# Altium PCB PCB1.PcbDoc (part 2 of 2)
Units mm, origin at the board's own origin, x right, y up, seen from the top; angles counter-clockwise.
Board outline 140.21 x 210.44 mm, 4 copper layers (Top Layer, Layer 1, Layer 2, Bottom Layer), stack 0.603 mm thick; 99 components, 45 nets, 371 pads, 603 vias.
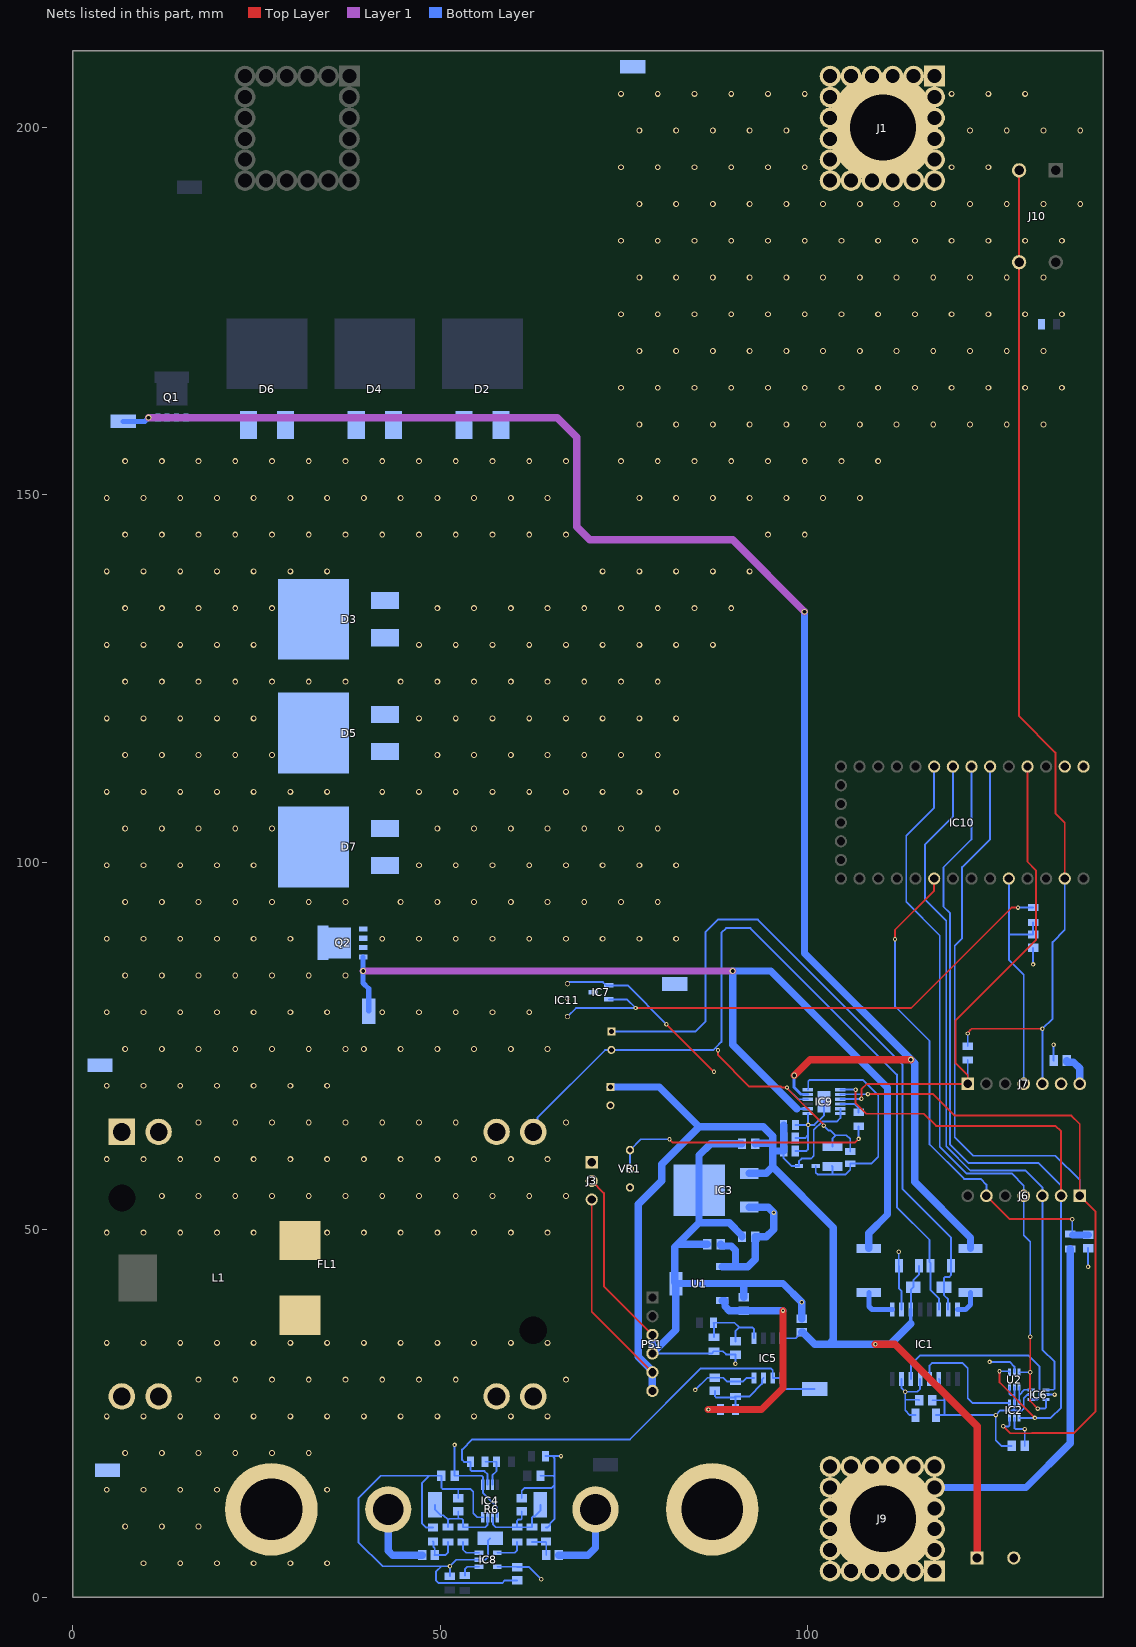
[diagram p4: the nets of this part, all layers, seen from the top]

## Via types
v1: diameter 0.8/0.8/0.8/0.8 (per signal layer), hole 0.5, Top Layer to Bottom Layer, 546 vias
v2: diameter 0.6, hole 0.3, Top Layer to Bottom Layer, 50 vias
v3: diameter 5, hole 5, Top Layer to Bottom Layer, 4 vias
v4: diameter 15, hole 9, Top Layer to Bottom Layer, 3 vias

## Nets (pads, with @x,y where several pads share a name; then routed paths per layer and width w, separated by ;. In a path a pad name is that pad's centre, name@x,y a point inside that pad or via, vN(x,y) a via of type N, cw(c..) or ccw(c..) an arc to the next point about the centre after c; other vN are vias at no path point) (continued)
ENABLE_PWM_HIN: IC2.3 IC9.2 IC10.28 J6.1 | length 164.4
  Top Layer w0.254: v2(108.204,68.453) 117.094,68.453 120.015,65.532 135.89,65.532 137.033,64.389 J6.1@137.033,54.61 139.192,52.451 139.192,25.273 136.271,22.352 130.556,22.352 130.51,22.306 127.554,22.306 v2(126.619,23.241)
  Bottom Layer w0.254: IC9.2@104.447,68.412 104.467,68.432 108.183,68.432 v2(108.204,68.453) ; IC10.28@124.841,113.03 124.841,103.169 121.031,99.359 121.031,89.662 120.015,88.646 120.015,62.611 122.555,60.071 133.731,60.071 137.033,56.769 J6.1@137.033,54.61 ; v2(126.619,23.241) 127.344,23.241 127.493,23.39 IC2.3@127.493,24.4
ENABLE_PWM_LIN: IC6.1 IC10.26 J6.3 | length 99.2
  Bottom Layer w0.254: IC10.26@119.761,113.03 119.761,106.208 115.933,102.38 115.951,102.362 115.951,94.996 118.872,92.075 118.872,61.341 122.165,58.048 129.658,58.048 131.953,55.753 131.953,33.655 133.604,32.004 133.604,28.358 133.455,28.209 IC6.1@132.445,28.209
FAULT_DRIVER: IC9.3 IC10.30 J7.1 R22.2 | length 71.1
  Top Layer w0.254: v2(107.315,67.818) 107.315,69.088 108.077,69.85 J7.1@121.793,69.85 121.793,70.993 120.142,72.644 120.142,78.486 131.064,89.408 131.064,98.933 129.921,100.076 IC10.30@129.921,113.03
  Bottom Layer w0.254: IC9.3@104.447,67.762 104.475,67.79 107.287,67.79 v2(107.315,67.818) ; J7.1@121.793,69.85 R22.2@121.793,73.091
GATE_Q1: IC9.11 Q1.4 R1.2 TP6.1 | length 229
  Top Layer w1: v1(98.171,70.993) 100.33,73.152 v1(114.046,73.152)
  Layer 1 w1: v1(10.287,160.528) 65.913,160.528 68.58,157.861 68.58,145.669 70.358,143.891 89.789,143.891 v1(99.568,134.112)
  Bottom Layer w0.254: Q1.4@11.536,160.528 Q1.4@11.557,160.549 ; IC9.11@100,68.435 IC9.11@100.023,68.412
  Bottom Layer w0.4: v1(98.171,70.993) 98.171,69.342 99.078,68.435 IC9.11@100,68.435
  Bottom Layer w0.7: TP6.1@6.858,160.02 9.779,160.02 v1(10.287,160.528) Q1.4@11.536,160.528
  Bottom Layer w1: v1(99.568,134.112) 99.568,87.63 114.554,72.644 114.554,56.515 122.174,48.895 R1.2@122.174,47.45
GATE_Q2: IC9.8 Q2.4 R2.2 TP12.1 | length 132.5
  Layer 1 w1: v1(39.497,85.217) v1(89.789,85.217)
  Bottom Layer w0.4: 98.511,66.462 IC9.8@100.023,66.462
  Bottom Layer w0.7: Q2.4@39.497,87.122 v1(39.497,85.217) 39.497,83.566 40.259,82.804 TP12.1@40.259,79.756
  Bottom Layer w1: 98.511,66.462 89.789,75.184 v1(89.789,85.217) 94.996,85.217 110.871,69.342 110.871,52.07 108.331,49.53 R2.2@108.331,47.45
GND: C1.2 C2.2 C3.2 C4.2 C5.2 C6.2 C7.2 C8.2 C9.2 C10.2 C11.2 C12.2 C13.2 C14.2 C15.2 C16.2 C17.2 C18.2 C21.2 C22.2 C25.2 C26.2 C27.2 D3.1 D3.3 D5.1 D5.3 D7.1 D7.3 IC1.2 IC1.13 IC1.15 IC2.2 IC3.2 IC4.4 IC5.4 IC6.2 IC7.3 IC8.2 IC9.7 IC9.13 IC10.32 IC11.2 J1.1 J1.2 J1.3 J1.4 J1.5 J1.6 J1.7 J1.8 J1.9 J1.10 J1.11 J1.12 J1.13 J1.14 J1.15 J1.16 J1.17 J1.18 J1.19 J1.20 J3.2 J7.6 J8.2 PS1.3 PS1.4 Q2.1 Q2.2 Q2.3 R5.2 R8.2 R10.2 R13.2 R14.2 R16.2 R20.2 TP2.1 TP8.1 TP11.1 U1.2 U1.4 U2.2 VR1.1 | length 267
  Top Layer w0.254: J3.2@70.612,56.642 72.263,54.991 72.263,42.291 PS1.3@78.867,35.687
  Bottom Layer w0.254: R20.2@49.022,9.459 48.072,9.459 47.498,10.033 47.498,15.494 48.514,16.51 ; R10.2@51.308,2.855 v2(51.308,4.191) ; C18.2@52.451,13.473 52.451,14.71 52.429,14.732 ; IC4.4@55.794,10.856 55.057,10.856 54.483,11.43 54.483,14.351 54.102,14.732 52.429,14.732 ; TP11.1@56.809,8.001 56.515,7.707 56.515,5.461 56.134,5.08 IC8.2@55.265,5.08 52.197,5.08 v2(51.308,4.191) ; C14.2@60.452,2.275 58.79,2.275 58.42,1.905 49.784,1.905 49.403,2.286 49.403,3.429 50.165,4.191 ; C15.2@61.087,13.473 61.087,14.478 61.468,14.859 65.151,14.859 65.532,15.24 ; C16.2@63.638,16.51 65.383,16.51 65.532,16.361 ; R13.2@64.323,19.177 65.278,19.177 ; R14.2@64.389,9.459 64.564,9.459 64.962,9.857 64.962,10.032 65.532,10.602 65.532,15.24 ; v2(66.425,19.181) 66.421,19.177 65.278,19.177 ; IC7.3@70.768,82.359 IC7.3@70.832,82.296 ; PS1.4@78.867,33.147 86.929,33.147 R8.2@87.249,33.467 88.453,33.467 88.9,33.02 90.159,33.02 C10.2@90.17,33.009 v2(90.17,31.75) ; v2(84.709,28.194) 86.371,29.856 C9.2@87.376,29.856 88.508,29.856 89.027,29.337 90.154,29.337 R5.2@90.17,29.321 91.17,29.321 91.649,29.8 IC5.4@92.71,29.8 ; C25.2@98.336,60.706 99.822,60.706 100.042,60.926 100.042,62.831 ; C27.2@98.336,62.484 99.695,62.484 100.042,62.831 ; C26.2@98.356,64.262 v2(100.076,64.262) ; IC9.7@100.023,65.812 100.023,64.315 v2(100.076,64.262) ; IC9.13@102.235,67.437 102.235,65.583 100.914,64.262 v2(100.076,64.262) ; v2(112.395,46.99) 112.395,45.102 C22.2@112.412,45.085 112.412,42.02 112.776,41.656 IC1.2@112.776,39.129 ; IC1.15@112.776,29.705 112.776,28.448 v2(113.284,27.94) ; C13.2@114.698,24.765 113.925,24.765 113.284,25.406 113.284,26.853 ; C5.2@115.178,26.797 115.122,26.853 113.284,26.853 ; IC1.13@115.316,29.705 115.316,28.321 114.935,27.94 v2(113.284,27.94) ; v2(124.76,32.004) 127.508,32.004 128.143,31.369 U2.2@128.143,30.591 ; IC2.2@128.143,24.4 128.143,23.009 128.292,22.86 v2(129.54,22.86) 129.54,20.585 C7.2@129.551,20.574 ; v2(130.683,86.106) C12.2@130.683,88.381 ; IC6.2@132.445,27.559 v2(133.604,27.559) ; C6.2@133.466,73.025 133.477,73.036 v2(133.477,75.184) ; v2(138.176,44.958) C11.2@138.176,47.487 ; 48.514,16.51 41.91,16.51 38.862,13.462 38.862,7.493 42.164,4.191 50.165,4.191 ; 48.514,16.51 C17.2@50.154,16.51 50.154,14.881 50.303,14.732 52.429,14.732 ; 50.165,4.191 v2(51.308,4.191) ; 65.278,19.177 65.532,18.923 65.532,16.361 ; 65.532,15.24 65.532,16.361 ; 100.042,62.831 100.042,64.228 v2(100.076,64.262) ; 113.284,26.853 v2(113.284,27.94)
  Bottom Layer w1: PS1.3@78.867,35.687 PS1.4@78.867,33.147 82.067,36.347 U1.4@82.067,42.672 ; C1.2@86.349,48.006 82.296,48.006 ; C3.2@91.062,49.022 91.062,49.172 89.307,50.927 85.217,50.927 ; C4.2@91.062,61.722 86.811,61.722 85.217,60.128 85.217,50.927 ; C2.2@91.313,40.778 91.313,42.672 ; C8.2@99.187,37.857 v2(99.187,40.132) 96.647,42.672 91.313,42.672 ; U1.4@82.067,42.672 81.915,42.824 81.915,47.625 82.296,48.006 ; U1.4@82.067,42.672 U1.2@88.367,42.672 91.313,42.672 ; 82.296,48.006 85.217,50.927
  other v1: 39.6,74.6 44.6,74.6 49.6,74.6 54.6,74.6 59.6,74.6 64.6,74.6 42.1,79.6 47.1,79.6 52.1,79.6 57.1,79.6 62.1,79.6 42.1,89.6 47.1,89.6 52.1,89.6 57.1,89.6 62.1,89.6 67.1,89.6 72.1,89.6 77.1,89.6 82.1,89.6 44.6,94.6 49.6,94.6 54.6,94.6 59.6,94.6 64.6,94.6 69.6,94.6 74.6,94.6 79.6,94.6 47.1,99.6 52.1,99.6 57.1,99.6 62.1,99.6 67.1,99.6 72.1,99.6 77.1,99.6 82.1,99.6 49.6,104.6 54.6,104.6 59.6,104.6 64.6,104.6 69.6,104.6 74.6,104.6 79.6,104.6 42.1,109.6 47.1,109.6 52.1,109.6 57.1,109.6 62.1,109.6 67.1,109.6 72.1,109.6 77.1,109.6 82.1,109.6 49.6,114.6 54.6,114.6 59.6,114.6 64.6,114.6 69.6,114.6 74.6,114.6 79.6,114.6 47.1,119.6 52.1,119.6 57.1,119.6 62.1,119.6 67.1,119.6 72.1,119.6 77.1,119.6 82.1,119.6 44.6,124.6 49.6,124.6 54.6,124.6 59.6,124.6 64.6,124.6 69.6,124.6 74.6,124.6 79.6,124.6 47.1,129.6 52.1,129.6 57.1,129.6 62.1,129.6 67.1,129.6 72.1,129.6 77.1,129.6 82.1,129.6 87.1,129.6 49.6,134.6 54.6,134.6 59.6,134.6 64.6,134.6 69.6,134.6 74.6,134.6 79.6,134.6 84.6,134.6 89.6,134.6 72.1,139.6 77.1,139.6 82.1,139.6 87.1,139.6 92.1,139.6 94.6,144.6 99.6,144.6 77.1,149.6 82.1,149.6 87.1,149.6 92.1,149.6 97.1,149.6 102.1,149.6 107.1,149.6 74.6,154.6 79.6,154.6 84.6,154.6 89.6,154.6 94.6,154.6 99.6,154.6 104.6,154.6 109.6,154.6 77.1,159.6 82.1,159.6 87.1,159.6 92.1,159.6 97.1,159.6 102.1,159.6 107.1,159.6 112.1,159.6 117.1,159.6 122.1,159.6 127.1,159.6 132.1,159.6 74.6,164.6 79.6,164.6 84.6,164.6 89.6,164.6 94.6,164.6 99.6,164.6 104.6,164.6 109.6,164.6 114.6,164.6 119.6,164.6 124.6,164.6 129.6,164.6 134.6,164.6 77.1,169.6 82.1,169.6 87.1,169.6 92.1,169.6 97.1,169.6 102.1,169.6 107.1,169.6 112.1,169.6 117.1,169.6 122.1,169.6 127.1,169.6 132.1,169.6 74.6,174.6 79.6,174.6 84.6,174.6 89.6,174.6 94.6,174.6 99.6,174.6 104.6,174.6 109.6,174.6 114.6,174.6 119.6,174.6 124.6,174.6 129.6,174.6 134.6,174.6 77.1,179.6 82.1,179.6 87.1,179.6 92.1,179.6 97.1,179.6 102.1,179.6 107.1,179.6 112.1,179.6 117.1,179.6 122.1,179.6 127.1,179.6 132.1,179.6 74.6,184.6 79.6,184.6 84.6,184.6 89.6,184.6 94.6,184.6 99.6,184.6 104.6,184.6 109.6,184.6 114.6,184.6 119.6,184.6 124.6,184.6 129.6,184.6 134.6,184.6 77.1,189.6 82.1,189.6 87.1,189.6 92.1,189.6 97.1,189.6 102.1,189.6 107.1,189.6 112.1,189.6 117.1,189.6 122.1,189.6 127.1,189.6 132.1,189.6 137.1,189.6 74.6,194.6 79.6,194.6 84.6,194.6 89.6,194.6 94.6,194.6 99.6,194.6 119.6,194.6 124.6,194.6 77.1,199.6 82.1,199.6 87.1,199.6 92.1,199.6 97.1,199.6 122.1,199.6 127.1,199.6 132.1,199.6 137.1,199.6 74.6,204.6 79.6,204.6 84.6,204.6 89.6,204.6 94.6,204.6 99.6,204.6 119.6,204.6 124.6,204.6 129.6,204.6
  other v4: 110.236,200.025
IN+AD8237: C15.1 IC4.2 R12.2 R21.2 TP9.1 | length 12.7
  Bottom Layer w0.254: IC4.2@57.094,10.856 57.192,10.758 57.192,9.864 57.547,9.509 R21.2@60.452,9.509 ; C15.1@61.087,11.673 61.087,10.69 60.938,10.541 60.601,10.541 60.452,10.392 R21.2@60.452,9.509 ; TP9.1@63.627,12.573 63.627,11.773 62.829,10.975 62.633,10.975 62.484,10.826 R12.2@62.484,9.509 R21.2@60.452,9.509
IN-AD8237: C18.1 IC4.3 R11.2 R19.2 TP10.1 | length 12.8
  Bottom Layer w0.254: TP10.1@49.276,12.573 49.276,11.938 50.074,11.14 50.433,11.14 51.054,10.519 ; R19.2@51.054,9.509 51.054,10.519 ; C18.1@52.451,11.673 52.451,10.817 52.6,10.668 ; IC4.3@56.444,10.856 56.444,9.835 56.118,9.509 R11.2@53.086,9.509 53.086,10.519 52.937,10.668 52.6,10.668 ; 51.054,10.519 51.203,10.668 52.6,10.668
NetC9_1: C9.1 IC5.3 R4.2 R5.1 | length 10.6
  Bottom Layer w0.254: C9.1@87.376,28.056 87.376,27.327 87.525,27.178 90.027,27.178 R5.1@90.17,27.321 ; R4.2@90.154,25.527 90.17,25.543 R5.1@90.17,27.321 ; IC5.3@93.98,29.8 93.782,29.602 93.782,29.012 92.091,27.321 R5.1@90.17,27.321
NetC10_1: C10.1 IC5.5 R7.2 R8.1 | length 11.2
  Bottom Layer w0.254: R8.1@87.249,35.367 87.249,37.272 R7.2@87.183,37.338 90.043,37.338 90.678,36.703 ; C10.1@90.17,34.809 90.17,36.195 90.678,36.703 ; IC5.5@92.71,35.224 92.71,36.449 92.456,36.703 90.678,36.703
NetC19_1: C19.1 C20.1 D1.1 IC1.7 | length 98.3
  Bottom Layer w0.254: C19.1@73.279,76.962 84.709,76.962 86.106,78.359 86.106,90.551 87.757,92.202 93.218,92.202 112.903,72.517 112.903,55.565 119.49,48.978 C20.1@119.49,45.085 119.49,43.798 119.253,43.561 118.708,43.561 118.559,43.412 D1.1@118.559,42.164 118.559,41.08 119.126,40.513 IC1.7@119.126,39.129
NetC23_2: C23.2 C24.2 D8.1 IC9.12 | length 32.2
  Bottom Layer w0.254: IC9.12@100.023,69.062 100.076,69.115 100.076,70.209 100.225,70.358 107.569,70.358 109.601,68.326 109.601,59.944 108.654,58.997 C24.2@105.791,58.997 105.791,58.166 105.156,57.531 103.527,57.531 ; D8.1@101.099,58.674 101.099,57.778 101.346,57.531 103.527,57.531 ; C23.2@103.298,58.674 C23.2@103.378,58.594 103.378,57.68 103.527,57.531
NetFB1_2: FB1.2 R12.1 R14.1 | length 3.7
  Bottom Layer w0.254: R12.1@62.484,7.509 64.339,7.509 64.428,7.42 FB1.2@64.428,5.715
NetFB2_2: FB2.2 R19.1 R20.1 | length 5.3
  Bottom Layer w0.254: R20.1@49.022,7.559 49.1,7.481 49.1,6.802 49.254,6.648 49.254,5.732 FB2.2@49.237,5.715 50.673,5.715 51.054,6.096 R19.1@51.054,7.509
NetFL1_A2: FL1.A2 FL1.A4 FL1.B2 FL1.B4 L1.1 R6.MH1 TP7.1
  other v1: 9.6,4.6 14.6,4.6 19.6,4.6 24.6,4.6 29.6,4.6 34.6,4.6 7.1,9.6 12.1,9.6 17.1,9.6 4.6,14.6 9.6,14.6 14.6,14.6 19.6,14.6 34.6,14.6 7.1,19.6 12.1,19.6 17.1,19.6 22.1,19.6 27.1,19.6 32.1,19.6 4.6,24.6 9.6,24.6 14.6,24.6 19.6,24.6 24.6,24.6 29.6,24.6 34.6,24.6 39.6,24.6 44.6,24.6 49.6,24.6 54.6,24.6 59.6,24.6 64.6,24.6 17.1,29.6 22.1,29.6 27.1,29.6 32.1,29.6 37.1,29.6 42.1,29.6 47.1,29.6 52.1,29.6 67.1,29.6 4.6,34.6 9.6,34.6 14.6,34.6 19.6,34.6 24.6,34.6 29.6,34.6 34.6,34.6 39.6,34.6 44.6,34.6 49.6,34.6 54.6,34.6 59.6,34.6 64.6,34.6
NetIC1_1: IC1.1 R2.1 | length 5.3
  Bottom Layer w0.7: R2.1@108.331,41.45 108.331,39.539 108.741,39.129 IC1.1@111.506,39.129
NetIC1_8: IC1.8 R1.1 | length 3.7
  Bottom Layer w0.7: IC1.8@120.396,39.129 121.504,39.129 122.174,39.799 R1.1@122.174,41.45
NetIC1_12: IC1.12 IC2.4 | length 17.5
  Bottom Layer w0.254: IC1.12@116.586,29.705 116.586,31.496 116.967,31.877 121.031,31.877 121.793,31.115 121.793,27.051 122.444,26.4 IC2.4@127.493,26.4
NetIC1_14: IC1.14 IC6.4 | length 26
  Bottom Layer w0.254: IC1.14@114.046,29.705 114.046,31.623 115.316,32.893 130.048,32.893 131.572,31.369 131.572,27.178 131.303,26.909 IC6.4@130.445,26.909
NetIC2_6: IC2.6 IC6.6 U2.4 | length 4.1
  Bottom Layer w0.254: IC2.6@128.793,26.4 128.793,27.495 ; U2.4@128.793,28.591 128.793,27.495 ; IC6.6@130.445,28.209 129.507,28.209 128.793,27.495
NetIC4_7: IC4.7 R15.2 R18.1 | length 4.9
  Bottom Layer w0.254: R15.2@56.118,18.415 R18.1@57.674,18.415 57.674,17.161 57.094,16.581 IC4.7@57.094,15.306
NetIC7_2: IC7.2 IC11.1 R17.1 | length 73.7
  Top Layer w0.254: v2(76.581,80.175) 114.084,80.175 127.746,93.837 v2(128.635,93.837)
  Bottom Layer w0.254: IC11.1@67.31,79 68.485,80.175 v2(76.581,80.175) 75.41,81.346 IC7.2@72.932,81.346 ; v2(128.635,93.837) R17.1@130.683,93.837
NetIC8_1: IC8.1 R9.1 | length 3
  Bottom Layer w0.254: R9.1@53.34,2.905 53.34,3.81 53.66,4.13 IC8.1@55.265,4.13
NetIC8_3: IC8.3 R11.1 | length 3.4
  Bottom Layer w0.254: R11.1@53.086,7.509 53.086,6.477 53.533,6.03 IC8.3@55.265,6.03
NetIC8_4: IC8.4 R21.1 | length 4
  Bottom Layer w0.254: IC8.4@57.765,6.03 60.132,6.03 60.452,6.35 R21.1@60.452,7.509
NetIC9_4: IC9.4 R23.1 | length 3.3
  Bottom Layer w0.254: IC9.4@104.447,67.112 106.333,67.112 106.934,66.511 R23.1@106.934,65.974
NetR23_2: R23.2 VR1.2 VR1.3 | length 36.4
  Top Layer w0.254: v2(81.199,62.311) 81.661,61.849 106.426,61.849 v2(106.934,62.357)
  Bottom Layer w0.254: VR1.2@75.819,58.293 VR1.3@75.819,60.833 77.297,62.311 v2(81.199,62.311) ; v2(106.934,62.357) R23.2@106.934,64.074
PWM_MC_SIGNAL_HIN: IC2.1 IC9.1 IC10.27 J6.2 U2.1 | length 159.4
  Top Layer w0.254: v2(106.527,69.062) 106.527,67.209 107.95,65.786 115.824,65.786 117.475,64.135 133.731,64.135 134.493,63.373 J6.2@134.493,54.61 ; v2(126.111,30.734) 126.111,29.21 v2(130.937,24.384)
  Bottom Layer w0.254: IC9.1@104.447,69.062 v2(106.527,69.062) ; IC10.27@122.301,113.03 122.301,103.124 118.491,99.314 118.491,93.98 119.38,93.091 119.38,61.595 121.92,59.055 131.445,59.055 134.493,56.007 J6.2@134.493,54.61 134.493,25.781 133.096,24.384 v2(130.937,24.384) 128.809,24.384 IC2.1@128.793,24.4 ; v2(126.111,30.734) 127.42,30.734 127.493,30.661 U2.1@127.493,30.591
PWM_MC_SIGNAL_LIN: IC6.3 IC10.25 J6.4 U2.3 | length 103.7
  Top Layer w0.254: v2(130.302,35.433) 130.294,35.425 130.294,30.599 v2(130.286,30.591) 130.286,26.686 v2(131.318,25.654)
  Bottom Layer w0.254: IC10.25@117.221,113.03 117.221,107.442 113.411,103.632 113.411,94.615 117.983,90.043 117.983,61.301 121.617,57.667 127.753,57.667 129.413,56.007 J6.4@129.413,54.61 129.413,49.276 130.302,48.387 v2(130.302,35.433) ; U2.3@128.793,30.591 v2(130.286,30.591) ; v2(131.318,25.654) 132.24,25.654 132.445,25.859 IC6.3@132.445,26.909
R_SHUNT+: FB1.1 R6.2 | length 10.6
  Bottom Layer w1: FB1.1@66.128,5.715 70.104,5.715 71.12,6.731 R6.2@71.12,11.938
R_SHUNT-: FB2.1 R6.1 | length 10.5
  Bottom Layer w1: R6.1@42.92,11.938 42.92,6.301 43.506,5.715 FB2.1@47.537,5.715
REF_1.5V: IC4.6 IC5.1 IC5.2 R15.1 TP3.1 | length 62.7
  Bottom Layer w0.254: IC4.6@56.444,15.306 56.444,16.708 56.007,17.145 54.251,17.145 54.102,17.294 54.102,18.399 53.229,18.399 52.959,18.669 52.959,20.066 54.356,21.463 75.819,21.463 85.471,31.115 94.996,31.115 95.25,30.861 IC5.2@95.25,29.8 IC5.1@96.52,29.8 96.52,28.702 96.901,28.321 TP3.1@100.965,28.321
SUPERCAPACITOR_SENSE: C11.1 IC10.9 J6.6 R3.2 | length 69.1
  Top Layer w0.254: v2(111.887,89.535) 111.887,90.805 117.221,96.139 IC10.9@117.221,97.79 ; J6.6@124.333,54.61 127.508,51.435 v2(136.017,51.435)
  Bottom Layer w0.254: v2(111.887,89.535) 111.887,80.391 116.586,75.692 116.586,61.621 121.301,56.905 123.562,56.905 124.333,56.134 J6.6@124.333,54.61 ; v2(136.017,51.435) 136.017,49.333 R3.2@136.063,49.287
  Bottom Layer w1: R3.2@136.063,49.287 C11.1@138.176,49.287
SUPERCAPACITOR_V+: J9.1 J9.2 J9.3 J9.4 J9.5 J9.6 J9.7 J9.8 J9.9 J9.10 J9.11 J9.12 J9.13 J9.14 J9.15 J9.16 J9.17 J9.18 J9.19 J9.20 R3.1 R6.MH2 | length 47.4
  Bottom Layer w1: J9.5@117.263,14.916 129.724,14.916 135.763,20.955 R3.1@135.763,47.387
  other v4: 110.236,10.668
SW_NET: C19.2 C20.2 C23.1 C24.1 D2.1 D2.3 D3.2 D4.1 D4.3 D5.2 D6.1 D6.3 D7.2 FL1.A1 FL1.A3 FL1.B1 FL1.B3 IC1.6 IC9.10 L1.2 Q1.1 Q1.2 Q1.3 Q2.5 Q2.6 TP5.1 | length 144.1
  Top Layer w0.254: v2(87.795,74.422) 87.803,74.414 87.803,73.741 92.075,69.469 96.38,69.469 96.491,69.358 v2(97.188,69.358) ; v2@97.282,69.406 97.255,69.379 97.255,69.199 102.197,64.257 v2(102.197,64.165)
  Bottom Layer w0.254: FL1.B3@62.658,63.305 63.254,63.901 63.254,65.286 72.43,74.462 C19.2@73.279,74.462 73.299,74.442 87.102,74.442 87.122,74.422 87.458,74.758 ; v2(87.795,74.422) 87.458,74.758 ; v2(97.188,69.358) 97.188,69.265 98.691,67.762 IC9.10@100.023,67.762 ; v2(102.197,64.165) 102.88,63.482 103.142,63.482 103.759,62.865 ; C23.1@103.378,61.294 103.378,62.39 103.759,62.771 103.759,62.865 ; C24.1@105.791,60.637 105.791,62.357 105.283,62.865 103.759,62.865 ; IC1.6@117.856,39.129 117.856,40.64 116.73,41.766 116.73,45.46 116.586,45.604 116.586,48.641 112.141,53.086 112.141,71.12 92.202,91.059 88.9,91.059 88.265,90.424 88.265,75.565 87.458,74.758
  other v1: 4.6,49.6 9.6,49.6 14.6,49.6 19.6,49.6 24.6,49.6 34.6,49.6 39.6,49.6 44.6,49.6 49.6,49.6 54.6,49.6 59.6,49.6 64.6,49.6 12.1,54.6 17.1,54.6 22.1,54.6 27.1,54.6 32.1,54.6 37.1,54.6 42.1,54.6 47.1,54.6 52.1,54.6 57.1,54.6 62.1,54.6 67.1,54.6 4.6,59.6 9.6,59.6 14.6,59.6 19.6,59.6 24.6,59.6 29.6,59.6 34.6,59.6 39.6,59.6 44.6,59.6 49.6,59.6 54.6,59.6 59.6,59.6 64.6,59.6 17.1,64.6 22.1,64.6 27.1,64.6 32.1,64.6 37.1,64.6 42.1,64.6 47.1,64.6 52.1,64.6 67.1,64.6 4.6,69.6 9.6,69.6 14.6,69.6 19.6,69.6 24.6,69.6 29.6,69.6 34.6,69.6 7.1,74.6 12.1,74.6 17.1,74.6 22.1,74.6 27.1,74.6 32.1,74.6 37.1,74.6 4.6,79.6 9.6,79.6 14.6,79.6 19.6,79.6 24.6,79.6 29.6,79.6 34.6,79.6 7.1,84.6 12.1,84.6 17.1,84.6 22.1,84.6 27.1,84.6 32.1,84.6 37.1,84.6 4.6,89.6 9.6,89.6 14.6,89.6 19.6,89.6 24.6,89.6 29.6,89.6 7.1,94.6 12.1,94.6 17.1,94.6 22.1,94.6 27.1,94.6 32.1,94.6 37.1,94.6 4.6,99.6 9.6,99.6 14.6,99.6 19.6,99.6 24.6,99.6 7.1,104.6 12.1,104.6 17.1,104.6 22.1,104.6 27.1,104.6 4.6,109.6 9.6,109.6 14.6,109.6 19.6,109.6 24.6,109.6 29.6,109.6 34.6,109.6 7.1,114.6 12.1,114.6 17.1,114.6 22.1,114.6 27.1,114.6 4.6,119.6 9.6,119.6 14.6,119.6 19.6,119.6 24.6,119.6 7.1,124.6 12.1,124.6 17.1,124.6 22.1,124.6 27.1,124.6 32.1,124.6 37.1,124.6 4.6,129.6 9.6,129.6 14.6,129.6 19.6,129.6 24.6,129.6 7.1,134.6 12.1,134.6 17.1,134.6 22.1,134.6 27.1,134.6 4.6,139.6 9.6,139.6 14.6,139.6 19.6,139.6 24.6,139.6 29.6,139.6 34.6,139.6 7.1,144.6 12.1,144.6 17.1,144.6 22.1,144.6 27.1,144.6 32.1,144.6 37.1,144.6 42.1,144.6 47.1,144.6 52.1,144.6 57.1,144.6 62.1,144.6 67.1,144.6 4.6,149.6 9.6,149.6 14.6,149.6 19.6,149.6 24.6,149.6 29.6,149.6 34.6,149.6 39.6,149.6 44.6,149.6 49.6,149.6 54.6,149.6 59.6,149.6 64.6,149.6 7.1,154.6 12.1,154.6 17.1,154.6 22.1,154.6 27.1,154.6 32.1,154.6 37.1,154.6 42.1,154.6 47.1,154.6 52.1,154.6 57.1,154.6 62.1,154.6 67.1,154.6
TEMP_SENSOR: C12.1 IC10.5 J7.4 R17.2 | length 33.7
  Bottom Layer w0.254: IC10.5@127.381,97.79 127.381,90.181 ; J7.4@129.413,69.85 129.413,84.709 127.381,86.741 127.381,90.181 ; R17.2@130.683,91.837 C12.1@130.683,90.181 127.381,90.181
VCC_3V: C2.1 C5.1 C7.1 C13.1 IC1.11 IC2.5 IC6.5 R4.1 U1.3 U2.5 U2.6 | length 65.6
  Top Layer w1: v2(86.487,25.527) 93.726,25.527 96.647,28.448 v2(96.647,38.989)
  Bottom Layer w0.254: v2(86.487,25.527) R4.1@88.154,25.527 ; C2.1@91.302,38.989 C2.1@91.313,38.978 ; C5.1@116.978,26.797 118.618,26.797 ; C13.1@117.458,24.765 118.618,24.765 ; IC1.11@117.856,29.705 117.921,29.64 117.921,28.51 118.618,27.813 118.618,26.797 ; U2.6@127.493,28.591 127.493,27.644 127.642,27.495 128.143,27.495 ; C7.1@127.751,20.574 126.365,20.574 125.603,21.336 v2(125.603,24.765) ; U2.5@128.143,28.591 128.143,27.495 ; IC6.5@130.445,27.559 130.372,27.486 129.848,27.486 129.413,27.051 129.413,25.654 129.159,25.4 127.889,25.4 ; 118.618,24.765 118.618,26.797 ; 118.618,24.765 v2(125.603,24.765) ; v2(125.603,24.765) 126.238,25.4 127.889,25.4 ; 127.889,25.4 128.143,25.654 IC2.5@128.143,26.4 128.143,27.495
  Bottom Layer w1: U1.3@88.367,40.372 88.392,40.347 88.742,40.347 88.742,39.575 89.328,38.989 C2.1@91.302,38.989 ; C2.1@91.313,38.978 96.636,38.978 v2(96.647,38.989)
VCC_3V_MCU: IC10.2 J7.5 J10.3 J10.4 R22.1 | length 140.4
  Top Layer w0.254: v2(121.793,76.708) 121.793,76.802 122.121,77.13 122.121,77.163 122.301,77.343 v2(131.953,77.343) ; J10.3@128.778,194.183 J10.4@128.778,181.683 128.778,119.888 133.731,114.935 133.731,106.68 135.001,105.41 IC10.2@135.001,97.79
  Bottom Layer w0.254: R22.1@121.793,74.991 v2(121.793,76.708) ; J7.5@131.953,69.85 v2(131.953,77.343) 133.35,78.74 133.35,89.154 135.001,90.805 IC10.2@135.001,97.79
VCC_5V: C1.1 C3.1 C6.1 C14.1 C17.1 IC3.3 IC4.1 IC4.5 IC7.1 IC8.5 IC10.33 IC11.3 J3.1 J7.7 U1.1 | length 72.1
  Top Layer w0.254: v2(80.772,77.978) v2(87.249,71.501)
  Bottom Layer w0.254: v2(51.954,20.712) C17.1@51.954,16.51 55.626,16.51 55.794,16.342 IC4.5@55.794,15.306 55.794,14.183 57.744,12.233 IC4.1@57.744,10.856 ; IC8.5@57.765,4.13 60.397,4.13 C14.1@60.452,4.075 62.092,4.075 v2(63.754,2.413) ; IC11.3@67.31,83.48 67.523,83.693 72.135,83.693 72.582,83.246 IC7.1@72.932,83.246 75.504,83.246 v2(80.772,77.978)
  Bottom Layer w1: C1.1@88.149,48.006 88.149,47.856 88.224,47.781 89.584,47.781 90.17,47.195 90.17,45.041 90.101,44.972 ; U1.1@88.367,44.972 90.101,44.972 ; IC3.3@92.067,53.072 94.629,53.072 v2(95.377,52.324) 95.377,50.038 94.361,49.022 C3.1@92.862,49.022 92.862,45.999 91.835,44.972 90.101,44.972 ; C6.1@135.266,73.025 135.266,72.875 135.341,72.8 136.193,72.8 137.033,71.96 J7.7@137.033,69.85
VCC_12V: C4.1 C8.1 C21.1 C22.1 C25.1 C26.1 C27.1 D1.2 D8.2 IC1.3 IC3.1 IC5.8 IC9.5 IC9.6 J3.3 J8.1 PS1.5 PS1.6 | length 214.5
  Top Layer w0.254: J3.3@70.612,54.102 70.612,38.862 PS1.5@78.867,30.607
  Top Layer w1: v2(109.22,34.417) 111.887,34.417 123.063,23.241 J8.1@123.063,5.334
  Bottom Layer w0.254: IC5.8@96.52,35.224 98.354,35.224 C8.1@98.962,35.832 ; C26.1@96.716,64.262 C26.1@96.736,64.242 ; C25.1@96.736,60.931 C25.1@96.736,60.706 96.736,59.728 97.79,58.674 D8.2@98.799,58.674 98.799,59.302 99.187,59.69 100.457,59.69 100.838,60.071 100.838,63.589 101.968,64.719 103.96,64.719 104.447,65.206 IC9.6@104.447,65.812 IC9.5@104.447,66.462 ; IC1.3@114.046,39.129 114.046,41.851 D1.2@114.359,42.164 114.418,42.223 114.418,43.171 115.172,43.925 C22.1@115.172,45.085
  Bottom Layer w0.5: 114.046,37.211 IC1.3@114.046,39.129
  Bottom Layer w1: C21.1@73.152,69.429 79.796,69.429 85.217,64.008 85.232,64.008 ; PS1.6@78.867,28.067 PS1.5@78.867,30.607 78.867,30.787 76.962,32.692 76.962,53.467 80.137,56.642 80.137,58.913 85.232,64.008 ; IC3.1@92.067,57.672 94.375,57.672 95.25,58.547 ; C4.1@92.862,61.722 92.912,61.722 92.937,61.747 95.25,61.747 ; C25.1@96.736,60.706 95.25,60.706 ; C25.1@96.736,60.931 C27.1@96.736,62.484 C26.1@96.736,64.242 ; C8.1@99.187,36.057 99.337,36.057 100.977,34.417 102.919,34.417 ; 114.046,37.211 111.252,34.417 v2(109.22,34.417) 102.919,34.417 ; 85.232,64.008 93.98,64.008 95.25,62.738 95.25,61.747 ; 95.25,58.547 95.25,60.706 ; 95.25,58.547 103.505,50.292 103.505,35.003 102.919,34.417 ; 95.25,60.706 95.25,61.747
pads on no net: FL1.1 FL1.2 IC1.4 IC1.5 IC1.9 IC1.10 IC1.16 IC9.9 IC10.1 IC10.3 IC10.4 IC10.7 IC10.8 IC10.11 IC10.12 IC10.13 IC10.14 IC10.15 IC10.16 IC10.17 IC10.18 IC10.19 IC10.20 IC10.21 IC10.22 IC10.23 IC10.31 L1.3
copper on no net:
  other v3: 5,5 135,5 5,205 135,205

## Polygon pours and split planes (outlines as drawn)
GND on Top Layer "GND" (solid, pour order 36): 73.533,210.185 139.827,210.185 139.827,184 139.827,181.494 139.827,155.067 115.062,155.067 84.963,124.968 84.963,81.28 68.707,81.28 66.167,78.74 66.167,73.279 65.405,72.517 38.481,72.517 38.481,84.582 38.481,87.88 38.481,91.694 40.64,93.853 40.64,137.922 42.291,139.573 69.977,139.573 73.533,143.129
NetFL1_A2 on Top Layer "Top Layer-NetFL1_A2" (solid, pour order 6): 1,1 36.576,1 36.576,22 68,22 68,42 25,42 25,39 1,39
SW_NET on Top Layer "GND" (solid, pour order 44): 0,161.544 65.151,161.544 68.453,158.242 68.453,141.097 39.37,141.097 37.846,139.573 37.846,68.961 65.659,68.961 67.818,66.802 67.818,45.72 1.524,45.72 0,47.244
BATTERY_V+ on Top Layer "GND" (solid, pour order 41): 66.612,164.719 71.819,169.926 71.819,210.439 0.064,210.439 0.064,162.433 18.86,162.433 21.019,164.592
SUPERCAPACITOR_V+ on Top Layer "Top Layer-SUPERCAPACITOR_V+" (solid, pour order 22): 78.867,1.016 119.873,1.016 119.873,22.016 99.873,22.016 99.873,20.016 95.25,20.016 78.867,20.016
GND on Bottom Layer "GND" (solid, pour order 18): 73.533,210.185 139.827,210.185 139.827,184 139.827,181.494 139.827,155.067 115.062,155.067 84.963,124.968 84.963,81.28 68.707,81.28 66.167,78.74 66.167,73.279 65.405,72.517 38.481,72.517 38.481,84.582 38.481,87.88 38.481,91.694 40.64,93.853 40.64,137.922 42.291,139.573 69.977,139.573 73.533,143.129
SW_NET on Bottom Layer "GND" (solid, pour order 17): 0,161.544 65.151,161.544 68.453,158.242 68.453,141.097 39.37,141.097 37.846,139.573 37.846,68.961 65.659,68.961 67.818,66.802 67.818,45.72 1.524,45.72 0,47.244
NetFL1_A2 on Bottom Layer "Top Layer-NetFL1_A2" (solid, pour order 45): 1,1 36.576,1 36.576,22 68,22 68,42 25,42 25,39 1,39
SUPERCAPACITOR_V+ on Bottom Layer "Top Layer-SUPERCAPACITOR_V+" (solid, pour order 24): 78.867,1.016 119.873,1.016 119.873,22.016 99.873,22.016 99.873,20.016 95.25,20.016 78.867,20.016
no net on Bottom Layer "GND" (solid, pour order 16): 0.635,162.179 0.508,162.306 0.635,162.179 0.762,162.306
BATTERY_V+ on Bottom Layer "GND" (solid, pour order 15): 66.612,164.719 71.819,169.926 71.819,210.439 0.064,210.439 0.064,162.433 18.86,162.433 21.019,164.592
NetFL1_A2 on Layer 1 "Top Layer-NetFL1_A2" (solid, pour order 47): 1,1 36.576,1 36.576,22 68,22 68,42 25,42 25,39 1,39
VCC_5V on Layer 1 "Layer 1-VCC_5V" (solid, pour order 50): 37.338,0.129 77.978,0.254 77.978,20.066 90.551,32.639 138.938,32.639 138.938,66.548 138.938,121.92 102.997,121.92 102.997,76.962 69.469,76.962 69.469,22.497 68.566,21.336 37.338,21.336
VCC_3V on Layer 1 "Layer 1-VCC_3V" (solid, pour order 34): 123.825,11.938 138.938,11.938 138.938,31.623 123.825,31.623 91.313,31.623 83.058,23.368 123.825,23.368
GND on Layer 1 "GND" (solid, pour order 37): 73.533,210.185 139.827,210.185 139.827,184 139.827,181.494 139.827,155.067 115.062,155.067 84.963,124.968 84.963,81.28 68.707,81.28 66.167,78.74 66.167,73.279 65.405,72.517 38.481,72.517 38.481,84.582 38.481,87.88 38.481,91.694 40.64,93.853 40.64,137.922 42.291,139.573 69.977,139.573 73.533,143.129
SW_NET on Layer 1 "GND" (solid, pour order 43): 0,161.544 65.151,161.544 68.453,158.242 68.453,141.097 39.37,141.097 37.846,139.573 37.846,68.961 65.659,68.961 67.818,66.802 67.818,45.72 1.524,45.72 0,47.244
BATTERY_V+ on Layer 1 "GND" (solid, pour order 40): 66.612,164.719 71.819,169.926 71.819,210.439 0.064,210.439 0.064,162.433 18.86,162.433 21.019,164.592
SUPERCAPACITOR_V+ on Layer 1 "Top Layer-SUPERCAPACITOR_V+" (solid, pour order 19): 78.867,1.016 119.873,1.016 119.873,22.016 99.873,22.016 99.873,20.016 95.25,20.016 78.867,20.016
GND on Layer 2 "Layer 2-GND" (solid, pour order 38): 0,0 140,0 140,210 0,210

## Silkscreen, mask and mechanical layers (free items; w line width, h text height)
Top Overlay:
  text "GND" at 91.94,200.557 h3
  text "ON/OFF" at 122.6,198.1 h3
  text "BAT V+" at 3.421,195.604 h3
  text "SC V+" at 101.465,20.725 h3
Bottom Overlay:
  text "Vcc" at 138.484,66.937 h1
  text "<- USB" at 138.611,62.365 h1
  text "PWM_L" at 128.905,56.388 h1.52 r270
  text "EN_L" at 131.445,56.388 h1.52 r270
  text "PWM_H" at 133.985,56.388 h1.52 r270
  text "EN_H" at 136.525,56.388 h1.52 r270
Top Solder:
  region: 5.913,180.175 65.913,180.175 65.913,80.175 5.913,80.175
